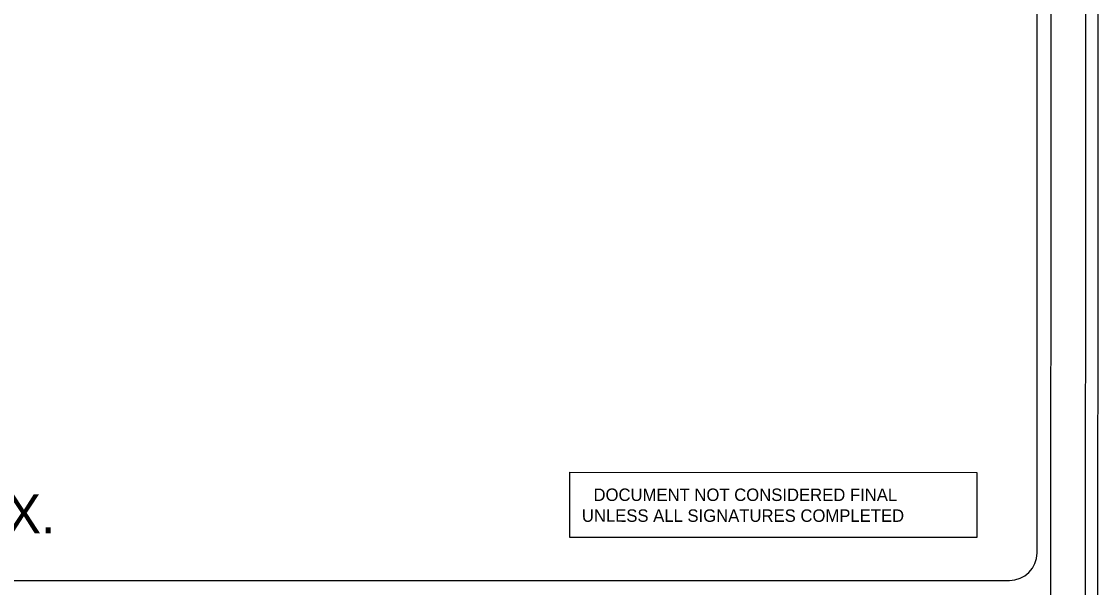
# Model space of a CAD drawing. Extents: x 2105791 to 2114488, y 667759 to 673441.
# Drawn here: x 2112480 to 2114488, y 668857 to 669912 of the extents above; entities that cross this region are included whole.
import ezdxf

# ---------------------------------------------------------------- set-up
doc = ezdxf.new("R2010")
doc.units = 0
for name, color, linetype in [('Old_Level_1', 7, 'Continuous'), ('Sheet Plot Border Inside CELL', 7, 'Continuous'), ('Sheet Plot Border Outside CELL', 7, 'Continuous'), ('Sheet Sticker Exception Certification CELL', 7, 'Continuous'), ('Sheet Title CELL', 7, 'Continuous')]:
    doc.layers.add(name, color=color, linetype=linetype)

msp = doc.modelspace()

# ---------------------------------------------------------------- linework, layer by layer
at = {"layer": 'Sheet Plot Border Inside CELL'}
msp.add_lwpolyline([(2105858.2, 667876.6), (2114463.6, 667875.1), (2114464.5, 673323.4), (2105859.1, 673324.8)], close=True, dxfattribs=at)
at = {"layer": 'Sheet Plot Border Outside CELL'}
msp.add_lwpolyline([(2114487.7, 673439.3), (2105792, 673440.8), (2105791, 667760.7), (2114486.8, 667759.2)], close=True, dxfattribs=at)
at = {"layer": 'Sheet Sticker Exception Certification CELL'}
for p, q in [((2113502, 668950.1), (2113502, 669071.5)), ((2113502, 669071.5), (2114261.1, 669071.3)), ((2114261.1, 669071.3), (2114261.1, 668949.9)), ((2114261.1, 668950), (2113502, 668950.1))]:
    msp.add_line(p, q, dxfattribs=at)
at = {"layer": 'Sheet Title CELL'}
msp.add_line((2106989.2, 668870.7), (2114321.7, 668869.5), dxfattribs=at)
for points in [[(2114399, 667940), (2114399.9, 673258.6)], [(2114373.4, 668921), (2114374.1, 673232.8)]]:
    msp.add_lwpolyline(points, dxfattribs=at)
msp.add_arc((2114321.7, 668921.3), 51.6, 269.9903, 359.9903, dxfattribs=at)

# ---------------------------------------------------------------- texts
at = {"layer": 'Old_Level_1'}
msp.add_text('NOTE: W-5601EY WAS DELETED.  THE WORK FROM W-5601EY WAS INCORPORATED INTO W-5601EX.', height=72.352, rotation=360, dxfattribs=at).set_placement((2107790.5, 668957.8))
at = {"layer": 'Sheet Sticker Exception Certification CELL'}
for s, p in [('DOCUMENT NOT CONSIDERED FINAL', (2113546.1, 669018)), ('UNLESS ALL SIGNATURES COMPLETED', (2113524.4, 668979.1))]:
    msp.add_text(s, height=23.237, rotation=359.9903, dxfattribs=at).set_placement(p)

doc.saveas('drawing.dxf')
